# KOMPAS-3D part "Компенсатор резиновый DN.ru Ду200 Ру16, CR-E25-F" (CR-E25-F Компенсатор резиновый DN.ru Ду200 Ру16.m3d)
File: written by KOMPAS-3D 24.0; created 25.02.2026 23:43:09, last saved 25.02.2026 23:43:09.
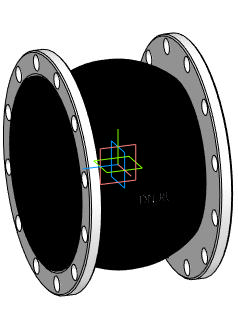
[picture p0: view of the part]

Document properties: Автор: DN.RU; Полное имя файла: D:\PROJECT CAD\DN.RU\...178(4)(ACTUALE). CR-E25-F Компенсатор резиновый DN.ru Ру10-16\DN200_PN16\CR-E25-F Компенсатор резиновый DN.ru Ду200 Ру16.m3d

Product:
- Body: Твердое тело2  | qty 1
    Масса: 43.457229
- Part/product: Компенсатор резиновый DN.ru Ду200 Ру16  | designation CR-E25-F
    Масса: 19.43
    Раздел спецификации: Прочие изделия
    Комментарий: D140-02179
    Примечание: D140-02179
    additional columns: Типовые

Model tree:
1. Твердое тело2  (labels: Твердое тело2)

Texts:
  CR-E25-F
